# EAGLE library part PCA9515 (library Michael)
I2C Bus voltage converter
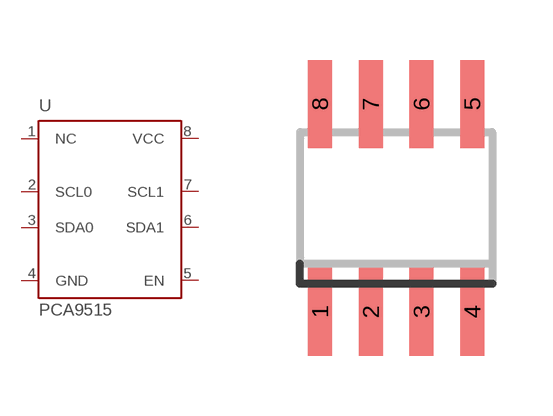
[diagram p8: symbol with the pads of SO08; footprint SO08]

Designator prefix -

## PCA9515  [SO08]
1  NC  nc
2  SCL0
3  SDA0
4  GND  pwr
5  EN  in
6  SDA1
7  SCL1
8  VCC  pwr

## Footprint SO08 (pad centres in mm)
Small Outline Package 8 NS Package M08A
smd 0.6 x 2.2: 1 -1.905,-2.6; 2 -0.635,-2.6; 3 0.635,-2.6; 4 1.905,-2.6; 5 1.905,2.6; 6 0.635,2.6; 7 -0.635,2.6; 8 -1.905,2.6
